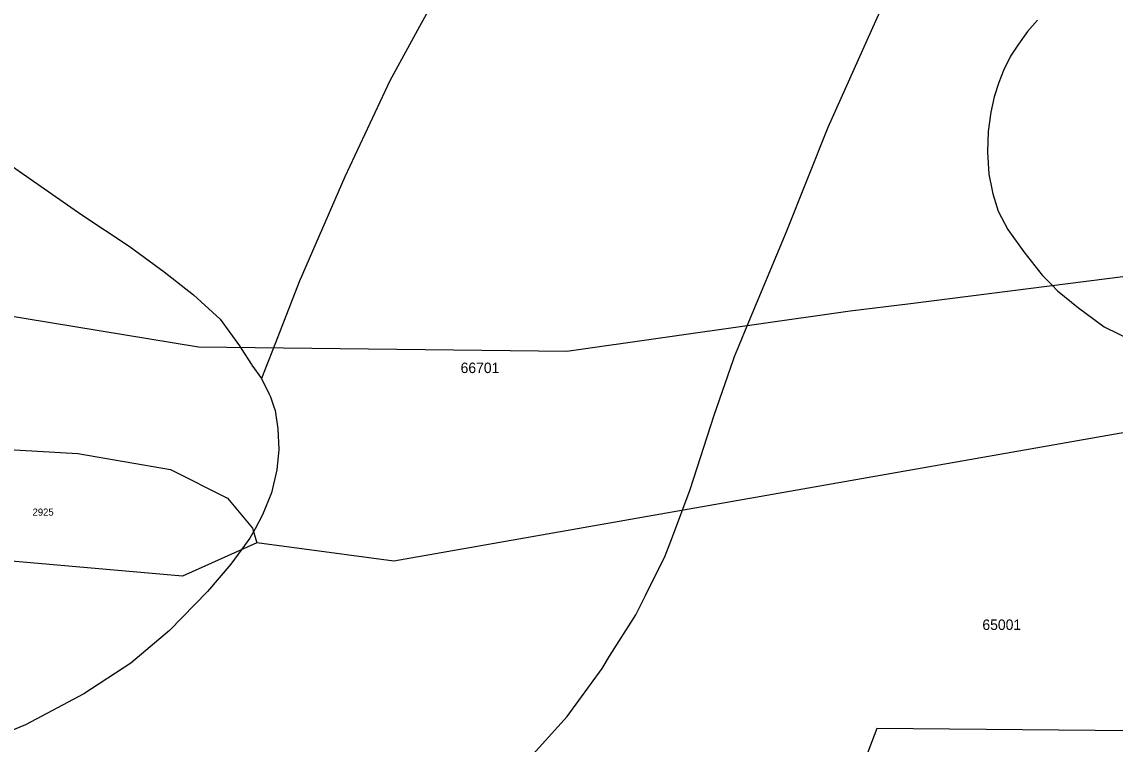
# Model space of a CAD drawing. Extents: x -546762 to -540209, y -1046851 to -1035694.
# Drawn here: x -543727.9 to -543465.8, y -1040274.6 to -1040101.5 of the extents above; entities that cross this region are included whole.
import ezdxf

# ---------------------------------------------------------------- set-up
doc = ezdxf.new("R2010")
doc.units = 0
for name, color, linetype in [('Vrstva 1', 7, 'Continuous'), ('Vrstva 18', 7, 'Continuous'), ('Vrstva 52', 7, 'Continuous'), ('Vrstva 53', 7, 'Continuous')]:
    doc.layers.add(name, color=color, linetype=linetype)

msp = doc.modelspace()

# ---------------------------------------------------------------- linework, layer by layer
at = {"layer": 'Vrstva 1'}
for points in [[(-543439.42, -1040159.43), (-543514.9, -1040169.02)], [(-543685.48, -1040179.44), (-543780.8, -1040163.76)], [(-543529.37, -1040170.81), (-543597.27, -1040180.48)], [(-543514.9, -1040169.02), (-543529.37, -1040170.81)], [(-543597.27, -1040180.48), (-543685.48, -1040179.44)], [(-543434.43, -1040194.73), (-543536.58, -1040212.72)], [(-543738.04, -1040203.57), (-543714.42, -1040204.93)], [(-543714.42, -1040204.93), (-543692.19, -1040208.74)], [(-543692.19, -1040208.74), (-543678.55, -1040215.62)], [(-543536.58, -1040212.72), (-543638.72, -1040230.7)], [(-543678.55, -1040215.62), (-543672.54, -1040222.77)], [(-543672.54, -1040222.77), (-543671.57, -1040226.33)], [(-543671.57, -1040226.33), (-543689.37, -1040234.32)], [(-543638.72, -1040230.7), (-543671.57, -1040226.33)], [(-543689.37, -1040234.32), (-543739.52, -1040229.88)], [(-543522.92, -1040270.79), (-543583.5, -1040429.98)], [(-543383.4, -1040272.12), (-543522.92, -1040270.79)]]:
    msp.add_lwpolyline(points, dxfattribs=at)
at = {"layer": 'Vrstva 52'}
for points in [[(-543585.33, -1040035.58), (-543602.59, -1040056.77), (-543603.74, -1040058.41), (-543614.35, -1040073.51), (-543629.77, -1040097.57), (-543632.54, -1040102.6), (-543639.7, -1040115.61), (-543650.42, -1040138.63), (-543661.4, -1040163.74), (-543667.62, -1040179.79), (-543669.12, -1040183.66)], [(-543606.85, -1040278.62), (-543597.18, -1040267.9), (-543588.81, -1040256.39), (-543586.99, -1040253.5), (-543580.71, -1040243.57), (-543578.38, -1040238.92), (-543573.65, -1040229.45), (-543571.92, -1040224.85), (-543567.64, -1040213.5), (-543561.89, -1040195.71), (-543557.31, -1040182.41), (-543557.05, -1040181.66), (-543555.87, -1040178.81), (-543554, -1040174.31), (-543544.7, -1040151.91), (-543534.64, -1040126.73), (-543522.14, -1040098.88), (-543516.61, -1040086.56)], [(-543484.4, -1040101.07), (-543486.79, -1040103.8), (-543489.01, -1040106.79), (-543490.88, -1040109.69), (-543492.59, -1040113.11), (-543493.7, -1040116.01), (-543494.81, -1040119.43), (-543495.58, -1040123.1), (-543496.26, -1040127.71), (-543496.43, -1040132.58), (-543496.43, -1040132.65), (-543496.09, -1040137.96), (-543495.31, -1040141.86), (-543495.15, -1040142.66), (-543493.87, -1040146.84), (-543491.57, -1040151.2), (-543487.72, -1040156.58), (-543483.29, -1040162.13), (-543481, -1040164.5), (-543479.61, -1040165.93), (-543474.57, -1040170.03), (-543468.42, -1040174.56), (-543461.43, -1040177.97)], [(-543753.99, -1040117.91), (-543735.69, -1040132.3), (-543713.47, -1040147.74), (-543702.12, -1040155.21), (-543693.76, -1040161.34), (-543686.74, -1040166.87), (-543680.31, -1040172.69), (-543675.68, -1040179.12), (-543675.3, -1040179.72), (-543672.8, -1040183.6), (-543672.7, -1040183.75), (-543670.39, -1040186.93)], [(-543669.12, -1040183.66), (-543670.39, -1040186.93)], [(-543670.39, -1040186.93), (-543668.57, -1040190.71), (-543668.26, -1040191.36), (-543667.53, -1040193.5), (-543667.15, -1040194.6), (-543666.47, -1040198.96), (-543666.3, -1040203.91), (-543666.73, -1040208.78), (-543668.01, -1040214.33), (-543670.14, -1040219.63), (-543671.97, -1040222.94), (-543673.21, -1040225.18), (-543675.14, -1040227.84)], [(-543675.14, -1040227.84), (-543677.74, -1040231.41), (-543683.38, -1040237.98), (-543692.43, -1040247.29), (-543701.73, -1040255.15), (-543713, -1040262.49), (-543727, -1040269.92), (-543737.67, -1040274.28)]]:
    msp.add_lwpolyline(points, dxfattribs=at)

# ---------------------------------------------------------------- texts
at = {"layer": 'Vrstva 18'}
msp.add_text('2925', height=1.7, dxfattribs=at).set_placement((-543725.29, -1040219.79))
at = {"layer": 'Vrstva 53'}
for s, p in [('66701', (-543622.7, -1040185.62)), ('65001', (-543497.64, -1040247.18))]:
    msp.add_text(s, height=2.5, dxfattribs=at).set_placement(p)

doc.saveas('drawing.dxf')
